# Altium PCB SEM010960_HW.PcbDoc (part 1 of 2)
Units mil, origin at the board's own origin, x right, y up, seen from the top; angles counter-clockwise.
Board outline 2559.06 x 1889.76 mil, 2 copper layers (Top Layer, Bottom Layer), stack 62 mil thick; 97 components, 58 nets, 246 pads, 75 vias.
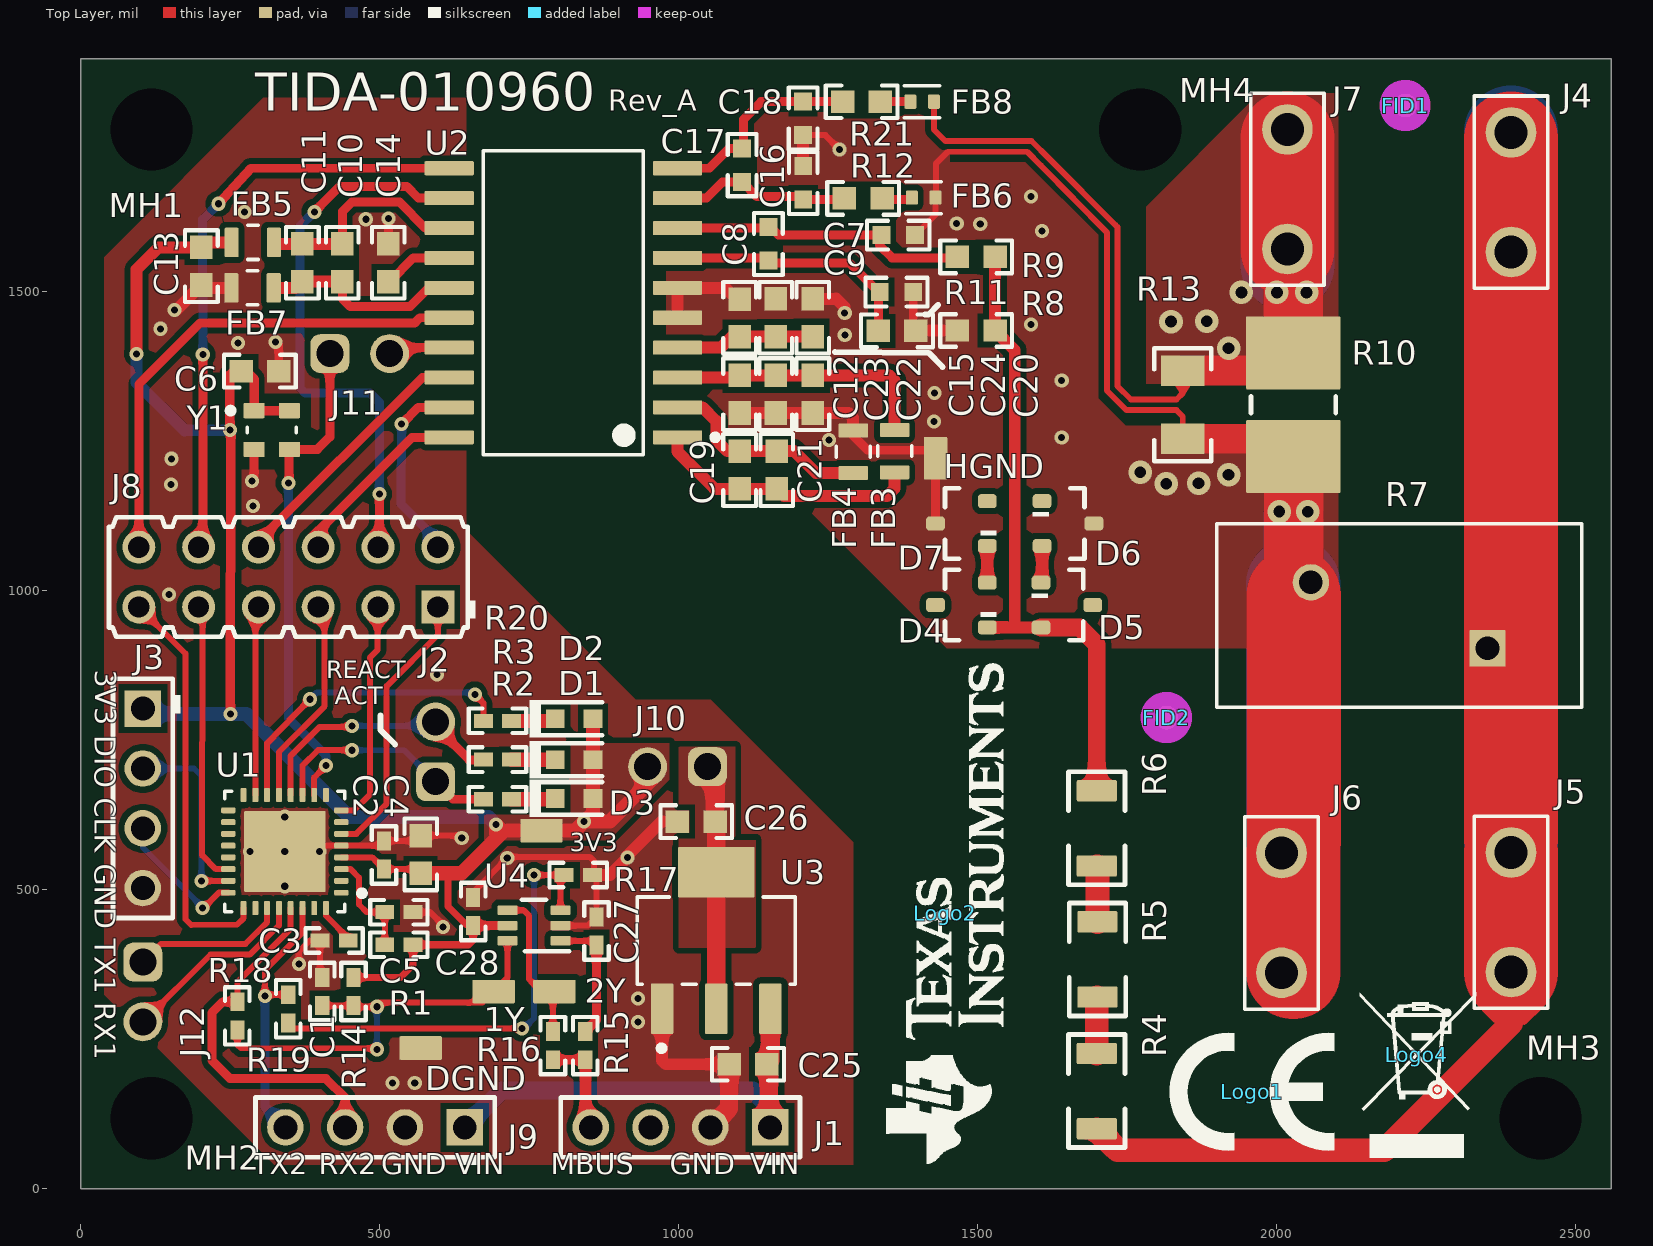
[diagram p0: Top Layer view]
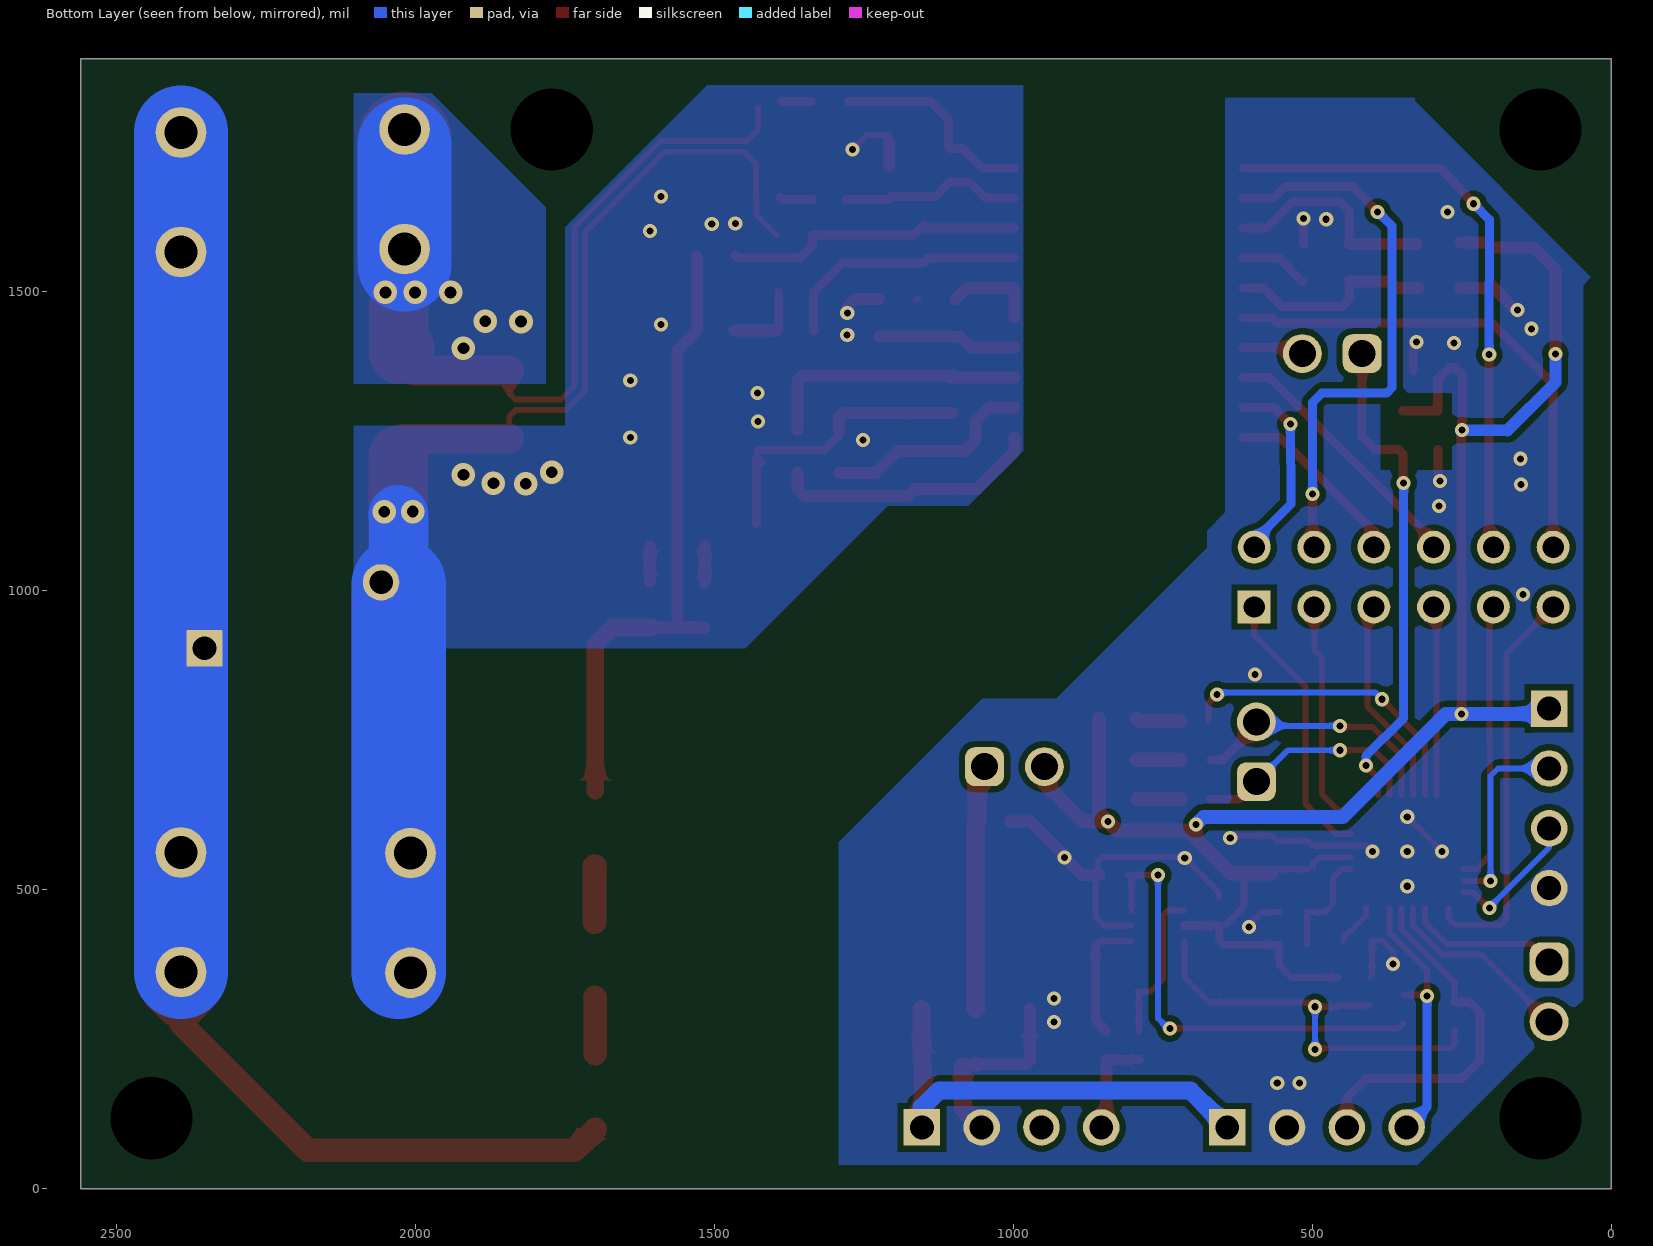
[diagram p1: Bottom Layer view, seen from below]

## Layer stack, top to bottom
Top Solder: solder mask 0.4, Solder Resist, Dk 3.5
Top Layer: signal copper 1.4
Dielectric1: core 59.2, FR-4 High Tg, Dk 4.8
Bottom Layer: signal copper 1.4
Bottom Solder: solder mask 0.4, Solder Resist, Dk 3.5

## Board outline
0,0 2559.06,0 2559.06,1889.76 0,1889.76

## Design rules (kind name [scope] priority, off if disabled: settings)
AcuteAngle [All] p1: minimum=1.50000000000000E+0001 checktracksonly=FALSE
AssemblyTestPointUsage [All] p1: valid=2
BoardOutlineClearance BoardOutlineClearance_MountingHoles [OnCopper and InComponentClass('Mounting Holes')] p1: gap=39.37 ignorepadtopadclearanceinfootprint=FALSE
BoardOutlineClearance BoardOutlineClearance_Poly [OnCopper and IsPoly] p2: gap=25 ignorepadtopadclearanceinfootprint=FALSE
BoardOutlineClearance [OnCopper and Not InComponentClass('Logo') and not InComponentClass('FiducialMark') and not InRegion(1000,500,4000,800) and not InPoly] p3: gap=40 ignorepadtopadclearanceinfootprint=FALSE
Clearance Clearance_Keepouts [((IsTrack Or IsArc) And Not InPoly) And IsFree and IsKeepOut vs ((IsTrack Or IsArc) And Not InPoly) And IsFree and IsKeepOut] p1: gap=0 ignorepadtopadclearanceinfootprint=FALSE
Clearance Clearance_Poly [InPolygon] p2: gap=10 ignorepadtopadclearanceinfootprint=TRUE
Clearance Clearance_FiducialMark [IsKeepOut and InComponentClass('FiducialMark') vs IsPad and InComponentClass('FiducialMark')] p3: gap=0 ignorepadtopadclearanceinfootprint=FALSE
Clearance [All] p4: gap=7.87 ignorepadtopadclearanceinfootprint=TRUE
ComponentClearance ComponentClearance_MountingHoles_FiducialMarks [InComponentClass('Mounting Holes') vs InComponentClass('FiducialMark')] p1: gap=50 collisioncheckmode=3 verticalgap=10 showdistances=FALSE
ComponentClearance ComponentClearance_Shunt [InComponentClass('Header') vs InComponentClass('Shunt')] p2: gap=0 collisioncheckmode=3 verticalgap=0 showdistances=FALSE
ComponentClearance ComponentClearance_Logo [InComponentClass('Logo')] p3: gap=30 collisioncheckmode=3 verticalgap=10 showdistances=FALSE
ComponentClearance ComponentClearance_ScrewToNut [(HasFootprint('NY PMS 440 0025 PH')) vs (HasFootprint('Keystone_1902C'))] p4: gap=5 collisioncheckmode=3 verticalgap=10 showdistances=FALSE
ComponentClearance ComponentClearance_MountingHoles [InComponentClass('Mounting Holes')] p5: gap=100 collisioncheckmode=3 verticalgap=100000 showdistances=FALSE
ComponentClearance ComponentClearance_SmallPassives [HasFootprint('0201*') or HasFootprint('0402*') or HasFootprint('0508') or HasFootprint('0603*') or HasFootprint('0612') or HasFootprint('0805*') or HasFootprint('0815*') or HasFootprint('0830*') or HasFootprint('1206*') or HasFootprint('1210*') or HasFootprint('1808*') or HasFootprint('1812*') or HasFootprint('1825*') or HasFootprint('2010*') or HasFootprint('2220*') or HasFootprint('2225*') or HasFootprint('2512*') or HasFootprint('2728*') or HasFootprint('3518*') vs HasFootprint('0201*') or HasFootprint('0402*') or HasFootprint('0508') or HasFootprint('0603*') or HasFootprint('0612') or HasFootprint('0805*') or HasFootprint('0815*') or HasFootprint('0830*') or HasFootprint('1206*') or HasFootprint('1210*') or HasFootprint('1808*') or HasFootprint('1812*') or HasFootprint('1825*') or HasFootprint('2010*') or HasFootprint('2220*') or HasFootprint('2225*') or HasFootprint('2512*') or HasFootprint('2728*') or HasFootprint('3518*')] p6: gap=14.96 collisioncheckmode=3 verticalgap=10 showdistances=FALSE
ComponentClearance ComponentClearance_THtoSMT [IsThruComponent vs IsSMTComponent] p7: gap=10 collisioncheckmode=3 verticalgap=10 showdistances=FALSE
ComponentClearance ComponentClearance_THtoTH [IsThruComponent vs IsThruComponent] p8: gap=20 collisioncheckmode=3 verticalgap=30 showdistances=FALSE
ComponentClearance [All] p9: gap=10 collisioncheckmode=3 verticalgap=10 showdistances=FALSE
DiffPairsRouting [All] p1: maxlimit=100 minlimit=10 mostfreqgap=10 toplayer_minwidth=15 toplayer_maxwidth=15 toplayer_prefwidth=15 bottomlayer_minwidth=15 bottomlayer_maxwidth=15 bottomlayer_prefwidth=15 maxuncoupledlength=1000
FabricationTestPointUsage TestPointUsage [All] p1: valid=2 allowmultiple=FALSE
FabricationTestpoint Testpoint [All] p1: side=3 testpointundercomponent=TRUE minsize=40 maxsize=100 preferedsize=60 minholesize=0 maxholesize=40 preferedholesize=32 testpointgrid=1 allowsidetop=TRUE allowsidebottom=TRUE usegrid=TRUE gridtolerance=0.01
FanoutControl Fanout_LCC [IsLCC] p1: bgadir=Out bgaviamode=Centered fanoutstyle=Auto fanoutdirection=Alternating viagrid=1 // Fanout_LCC (Default Rule)
FanoutControl Fanout_BGA [IsBGA] p2: bgadir=Out bgaviamode=Centered fanoutstyle=Auto fanoutdirection=Alternating viagrid=1 // Fanout_BGA (Default Rule)
FanoutControl Fanout_Default [All] p4: bgadir=Out bgaviamode=Centered fanoutstyle=Auto fanoutdirection=Alternating viagrid=1 // Fanout_Default (Default Rule)
FanoutControl Fanout_Small [(CompPinCount < 5)] p5: bgadir=Out bgaviamode=Centered fanoutstyle=Auto fanoutdirection=OutThenIn viagrid=1 // Fanout_Small (Default Rule)
HoleSize [All] p1: absolutevalues=TRUE maxlimit=251 minlimit=5 maxpercent=80.000 minpercent=20.000
MinimumAnnularRing MinimumAnnularRing_ThermalPadVias [IsVia and InAnyComponent] p1: minimumring=5.91
MinimumAnnularRing [All] p2: minimumring=5
MinimumSolderMaskSliver MinimumSolderMaskSliver_Logo [InComponentClass('Logo') vs InComponentClass('Logo')] p1: minsoldermaskwidth=0.7
MinimumSolderMaskSliver [All] p2: minsoldermaskwidth=0
PlaneConnect [All] p1: planeconnectstyle=Direct reliefexpansion=10 reliefentries=4 reliefconductorwidth=10 reliefairgap=10
PolygonConnect [All] p1: connectstyle=Direct reliefconductorwidth=10 reliefentries=4 polygonreliefangle="90 Angle" airgapwidth=10
RoutingVias ThermalPadVias [IsVia and InAnyComponent] p1: holewidth=7.87 width=19.68 viastyle="Through Hole" minholewidth=7.87 minwidth=19.68 maxholewidth=12.99 maxwidth=23.62
RoutingVias [All] p2: holewidth=16 width=34 viastyle="Through Hole" minholewidth=5 minwidth=5 maxholewidth=40 maxwidth=65
SilkToBoardRegionClearance [Not ((IsComment or IsDesignator) And (Hide <> 'False')) and not InRegion(1000,500,4000,800)] p1:
SilkToSilkClearance SilkToSilkClearance_Pb-FreeLogo [(HasFootprint('Pb-Free_Overlay_Medium') OR HasFootprint('Pb-Free_Overlay_Small')) vs (HasFootprint('Pb-Free_Overlay_Medium') OR HasFootprint('Pb-Free_Overlay_Small'))] p1: silktosilkclearance=0
SilkToSilkClearance [All] p2: silktosilkclearance=0
SilkToSolderMaskClearance SilkToComponentPadClearance [(IsPad or IsFill or IsRegion) and InAnycomponent] p1: minsilkscreentomaskgap=0 clearancetoexposedcopper=TRUE
SilkToSolderMaskClearance "Silk to Solder Mask Opening" [All] p2: minsilkscreentomaskgap=0 clearancetoexposedcopper=FALSE
SolderMaskExpansion [All] p1: expansion=1.97 istentingtop=FALSE
UnRoutedNet [All] p1: checkbadconnections=TRUE
Width [All] p1: maxlimit=157.48 minlimit=6 preferedwidth=10 checkconnectedcopper=TRUE
14 further rules are at their usual default settings.

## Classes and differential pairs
component class SEM010960_HW_MSPM0: 1Y 2Y 3V3 C1 C2 C3 C4 C5 C6 C25 C26 C27 C28 D1 D2 D3 J1 J2 J3 J8 J9 J10 J12 R1 R2 R3 R14 R15 R16 R17 R18 R19 R20 U1 U3 U4 Y1
component class SEM010960_HW_AMC: C7 C8 C9 C10 C11 C12 C13 C14 C15 C16 C17 C18 C19 C20 C21 C22 C23 C24 D4 D5 D6 D7 DGND FB3 FB4 FB5 FB6 FB7 FB8 HGND J4 J5 J6 J7 J11 R4 R5 R6 R7 R8 R9 R10 R11 R12 R13 R21 U2
component class Header: J1 J2 J3 J8 J9 J10 J11 J12
component class Logo: Logo2
component class SEM010960_HW_Hardware: FID1 FID2 Logo1 Logo2 Logo4 MH1 MH2 MH3 MH4 ZZ1 ZZ2 ZZ3 ZZ4
component class FiducialMark: FID1 FID2
component class AssemblyNote: ZZ1 ZZ2 ZZ3 ZZ4

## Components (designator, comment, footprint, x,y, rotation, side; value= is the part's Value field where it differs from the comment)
1Y "Testpoint_Gray" Harwin_S2761-46R 690.22,330.04 r180 top
2Y "Testpoint_Gray" Harwin_S2761-46R 791.78,330.04 r180 top
3V3 "Testpoint_Gray" Harwin_S2761-46R 770.28,599.28 r180 top
C1 "C0402C101J3GACTU" 0402 403.54,330.04 r90 top value=100pF
C2 "GRM155R61A105KE15D" 0402 506.78,558.33 r90 top value=1uF
C3 "GRM155R61C474KE01" 0402 423.49,415.31 r0 top value=0.47uF
C4 "GRM188R61A106KAALD" 0603 568.12,559.29 r270 top value=10uF
C5 "C1005X7R1C103K050BA" 0402 531.78,462.82 r0 top value=0.01uF
C6 "LMK107B7105KA-T" 0603 299.36,1367.63 r0 top value=1uF
C7 "885012006057" 0603_HV 1366.91,1595.02 r0 top value=100pF
C8 "C0603C472J1GAC7867" 0603_HV 1149.9,1580.32 r270 top value=4700pF
C9 "885012006057" 0603_HV 1364,1499.91 r180 top value=100pF
C10 "C0603C102K5RACTU" 0603 437.16,1548.83 r270 top value=1000pF
C11 "C0603C105K3RACTU" 0603 370.41,1548.83 r90 top value=1uF
C12 "885012006057" 0603 1101.57,1329.08 r90 top value=100pF
C13 "C0603C105K3RACTU" 0603 201.52,1543.15 r90 top value=1uF
C14 "C1608X7R1H104K080AA" 0603 514.1,1548.83 r90 top value=0.1uF
C15 "885012006057" 0603 1101.57,1456.52 r270 top value=100pF
C16 "885012006057" 0603_HV 1207.99,1682.52 r90 top value=100pF
C17 "C0603C472J1GAC7867" 0603_HV 1105.92,1712.12 r90 top value=4700pF
C18 "885012006057" 0603_HV 1207.7,1790.18 r90 top value=100pF
C19 "C0603C102K5RACTU" 0603 1101.57,1202.29 r90 top value=1000pF
C20 "C1608X7R1H104K080AA" 0603 1223.92,1456.91 r90 top value=0.1uF
C21 "C0603C105K3RACTU" 0603 1163.8,1202.29 r270 top value=1uF
C22 "C1608X7R1H104K080AA" 0603 1224.17,1329.08 r270 top value=0.1uF
C23 "C0603C102K5RACTU" 0603 1162.23,1329.08 r270 top value=1000pF
C24 "C0603C102K5RACTU" 0603 1162.23,1456.91 r90 top value=1000pF
C25 "CGA3E1X7R1V105K080AE" 0603 1115.61,208.42 r180 top value=1uF
C26 "GRM188Z71C225KE43" 0603 1029.13,614.27 r180 top value=2.2uF
C27 "C0402C101J3GACTU" 0402 862.2,431.33 r90 top value=100pF
C28 "04023C103JAT2A" 0402 655.94,463.84 r90 top value=0.01uF
D1 "150060VS75000" WL-SMCW_GREEN 824.74,653.05 r0 top value=Green
D2 "150060YS75000" WL-SMCW_YELLOW 824.74,717.62 r0 top value=Yellow
D3 "150060RS75000" WL-SMCW_RED 824.74,786.21 r0 top value=Red
D4 "BAV199-TP" SOT-23L 1472.56,976.43 r180 top value=70V
D5 "BAV199-TP" SOT-23L 1648.9,976.43 r0 top value=70V
D6 "BAV199-TP" SOT-23L 1650.78,1112.76 r0 top value=70V
D7 "BAV199-TP" SOT-23L 1472.56,1112.76 r180 top value=70V
DGND "Testpoint_Gray" Harwin_S2761-46R 568.12,235.62 r180 top
FB3 "BLM21HE472SH1L" FP-BLM21HE472SH1L_0805-MFG 1360.91,1233.79 r90 top
FB4 "BLM21HE472SH1L" FP-BLM21HE472SH1L_0805-MFG 1291.55,1232.81 r90 top
FB5 "BLM21HE472SH1L" FP-BLM21HE472SH1L_0805-MFG 287.53,1582.83 r180 top
FB6 "74269244182" FP-74269244182_0402-MFG 1409.42,1657.7 r0 top
FB7 "BLM21HE472SH1L" FP-BLM21HE472SH1L_0805-MFG 286.99,1506.91 r180 top
FB8 "74269244182" FP-74269244182_0402-MFG 1406.9,1818.18 r0 top
FID1 "Fiducial" Fiducial10-20 2214.57,1811.83 r0 top
FID2 "Fiducial" Fiducial10-20 1815.21,788.17 r0 top
HGND "Testpoint_Gray" Harwin_S2761-46R 1429.25,1222.13 r270 top
J1 "PBC04SAAN" Sullins_xxC04SAAN 1002.59,102.93 r180 top
J2 "61300211121" WURTH_61300211121 593.26,731.01 r90 top
J3 "PBC04SAAN" Sullins_xxC04SAAN 103.57,653.05 r270 top
J4 "63824-1" FP-63824-1_CONN_7MM92_3MM11-MFG 2391.73,1666.9 r90 top
J5 "63824-1" FP-63824-1_CONN_7MM92_3MM11-MFG 2391.73,462.6 r270 top
J6 "63824-1" FP-63824-1_CONN_7MM92_3MM11-MFG 2007.87,461.48 r270 top
J7 "63824-1" FP-63824-1_CONN_7MM92_3MM11-MFG 2017.72,1671.9 r270 top
J8 "802-10-012-10-001000" Mill-Max_802-10-012-10-001000 346.88,1023.2 r180 top
J9 "PBC04SAAN" Sullins_xxC04SAAN 491.91,102.93 r180 top
J10 "61300211121" WURTH_61300211121 997.78,706.13 r180 top
J11 "61300211121" WURTH_61300211121 466.29,1396.93 r0 top
J12 "61300211121" WURTH_61300211121 103.57,329.33 r270 top
Logo1 "CE Mark" CE_Mark_5mm 1958.66,162.33 r0 top
Logo2 "Texas Instruments" TI_Stacked_Overlay_Small 1445.3,460.66 r90 top
Logo4 "WEEE logo" WEEE_Minimum 2234.25,224.41 r0 top
MH1 "MTG_NoPads" NPTH125mil#1 105.6,1764.12 r0 top
MH2 "MTG_NoPads" NPTH125mil#2 118.11,118.11 r0 top
MH3 "MTG_NoPads" NPTH125mil#3 2450.79,127.95 r0 top
MH4 "MTG_NoPads" NPTH125mil#4 1771.65,1736.37 r0 top
R1 "RC0402FR-0747KL" 0402 531.78,408.3 r0 top value=47.0k
R2 "RC0402FR-07820RL" 0402 696.7,651.64 r0 top value=820
R3 "RC0402FR-07820RL" 0402 696.7,717.95 r0 top value=820
R4 "TNPV1206330KBEEN" TNPV1206 1698.88,163.57 r270 top value=330k
R5 "TNPV1206330KBEEN" TNPV1206 1699.92,383.68 r270 top value=330k
R6 "TNPV1206330KBEEN" TNPV1206 1698.88,602.9 r90 top value=330k
R7 "B72214S2461K101" FP-B72214S2461K101_RADIAL-MFG 2204.72,959.21 r180 top
R8 "RG1608P-751-B-T5" 0603 1497.28,1435.59 r0 top value=750
R9 "CRCW060349R9FKEA" 0603 1497.28,1558.67 r180 top value=49.9
R10 "CRE2512-FZ-R003E-3" CRE2512-R1_R4 2027.56,1311.46 r270 top value=0.003
R11 "CRCW060349R9FKEA" 0603 1364.86,1434.86 r180 top value=49.9
R12 "CRCW060349R9FKEA" 0603 1308.29,1656.49 r180 top value=49.9
R13 "CRF1206-FZ-R001ELF" 1206 1842.71,1311.46 r270 top value=0.001
R14 "CRCW040210K0DHEDP" 0402 455.94,330.04 r90 top value=10.0k
R15 "CRCW040210K0DHEDP" 0402 843.53,239.71 r270 top value=10.0k
R16 "CRCW040210R0FKED" 0402 789.37,239.71 r270 top value=10.0
R17 "CRCW040210K0DHEDP" 0402 831.72,524.84 r180 top value=10.0k
R18 "RC0402JR-070RL" 0402 261.68,289.33 r270 top value=0
R19 "RC0402JR-070RL" 0402 346.85,301.14 r270 top value=0
R20 "RC0402FR-07820RL" 0402 696.7,782.68 r0 top value=820
R21 "CRCW060349R9FKEA" 0603 1305.52,1818.18 r180 top value=49.9
U1 "MSPM0G1106TRHBR" RHB0032N-MFG 340.94,564.23 r180 top
U2 "AMC131M03DFM" DFM0020A-MFG 806.83,1481.91 r180 top
U3 "TLV76133DCYR" DCY0004A-MFG 1062.59,415.31 r90 top
U4 "SN74LVC2G07DCKT" DCK0006A_N 757.73,440.38 r180 top
Y1 "LMK6CxxxDLF" DLF0004A-MFG 319.15,1269.09 r0 top
ZZ1 "This Assembly Note is for PCB labels only" AssemblyNoteLabel 185,3938 r0 top
ZZ2 "These assemblies are ESD sensitive, ESD precautions shall be observed." AssemblyNote 185,3829.11 r0 top
ZZ3 "These assemblies must be clean and free from flux and all contaminants. Use of no clean flux is not acceptable." AssemblyNote 185,3740.56 r0 top
ZZ4 "These assemblies must comply with workmanship standards IPC-A-610 Class 2, unless otherwise specified." AssemblyNote 185,3652 r0 top

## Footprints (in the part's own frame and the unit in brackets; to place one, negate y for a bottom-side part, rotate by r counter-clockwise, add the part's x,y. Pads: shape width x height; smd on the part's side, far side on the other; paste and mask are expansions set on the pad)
0402 [mm] "0402 from SM-752 data"
  rect 0.8x0.6 smd: 1(-0.6,0) 2(0.6,0)
  silkscreen extent -1.22,-0.52 1.22,0.52, body extent -0.55,-0.3 0.55,0.3, height 0.6
0603 [mm] "0603 from SM-752 data"
  rect 1x0.95 smd: 1(-0.8,0) 2(0.8,0)
  silkscreen extent -1.52,-0.69 1.52,0.69, body extent -0.87,-0.47 0.87,0.47, height 1
0603_HV [mil] "Ernesto recommended land pattern.  26 mil between pads."
  rect 30x30 smd: 1(-28,0) 2(28,0)
  silkscreen extent -52,-24 52,24, body extent -34,-19 34,19, height 39
1206 [mm] "1206 from SM-752 data"
  rect 1.3x1.85 smd: 1(-1.45,0) 2(1.45,0)
  silkscreen extent -2.4,-1.21 2.4,1.21, body extent -1.7,-0.9 1.7,0.9, height 1.35
AssemblyNote [mil] "Assembly Note"
AssemblyNoteLabel [mil] "Assembly Note for PCB Labels"
CE_Mark_5mm [mil] "Minimum text height for CE Mark"
  silkscreen extent -138,-98 138,98
CRE2512-R1_R4 [mm] "SMD, 2-Leads, Body 6.45x3.35mm"
  rrect3% 3.1x4 smd: 1(-2.2,0) 2(2.2,0)
  silkscreen extent -0.35,-1.8 0.35,1.8, body extent -3.32,-1.77 3.33,1.78, height 0.9
DCK0006A_N [mm] "SOT23, 6-Leads, Body 2x1.3mm, Pitch 0.65mm, Lead Span 2.1mm, IPC Medium Density"
  rrect25% 0.85x0.4 smd: 1(-1.125,0.65) 2(-1.125,0) 3(-1.125,-0.65) 4(1.125,-0.65) 5(1.125,0) 6(1.125,0.65)
  silkscreen extent -1.5,-1.09 0.51,1.09, body extent -1.14,-1 1.14,1, height 0.95
DCY0004A-MFG [mm]
  rrect11% 2.15x0.95 smd paste+0 mask+0: 1(-2.9,2.3) 2(-2.9,0) 3(-2.9,-2.3)
  rrect5% 2.15x3.25 smd paste+0 mask+0: 4(2.9,0)
  silkscreen extent -4.7,-3.35 1.85,3.35, body extent -4.08,-3.45 4.08,3.45, height 0.25
DFM0020A-MFG [mm]
  rrect17% 2.1x0.6 smd paste+0 mask+0: 1(-4.85,5.715) 2(-4.85,4.445) 3(-4.85,3.175) 4(-4.85,1.905) 5(-4.85,0.635) 6(-4.85,-0.635) 7(-4.85,-1.905) 8(-4.85,-3.175) 9(-4.85,-4.445) 10(-4.85,-5.715) 11(4.85,-5.715) 12(4.85,-4.445) 13(4.85,-3.175) 14(4.85,-1.905) 15(4.85,-0.635) 16(4.85,0.635) 17(4.85,1.905) 18(4.85,3.175) 19(4.85,4.445) 20(4.85,5.715)
  silkscreen extent -6.57,-6.47 3.4,6.47, body extent -6,-6.72 6,6.72, height 0.25
DLF0004A-MFG [mm]
  rrect15% 0.9x0.65 smd paste-1000 mask+0: 1(-0.75,0.825) 2(-0.75,-0.825) 3(0.75,-0.825) 4(0.75,0.825)
  silkscreen extent -1.87,-0.13 1.05,0.95, body extent -1.3,-1.4 1.3,1.4, height 0.25
Fiducial10-20 [mm]
  round 1 smd mask+0.5: 1(0,0)
  Top Layer keep-out circle w1.178: c0,0 r0.5
FP-63824-1_CONN_7MM92_3MM11-MFG [mm]
  round 2.15 hole 1.4 paste-1000 mask+0: 1(-2.54,0) 1(2.54,0)
  silkscreen extent -4.09,-1.56 4.09,1.56, body extent -3.96,-1.54 3.96,1.54, height 10.88
FP-74269244182_0402-MFG [mm]
  rrect20% 0.5x0.6 smd paste+0 mask+0: 1(-0.5,0) 2(0.5,0)
  silkscreen extent -0.75,-0.67 0.75,0.67, body extent -0.85,-0.4 0.85,0.4, height 0.25
FP-B72214S2461K101_RADIAL-MFG [mm]
  rrect6% 1.55x1.55 hole 1 paste-1000 mask+0: 1(-3.75,1.4)
  round 1.55 hole 1 paste-1000 mask+0: 2(3.75,-1.4)
  silkscreen extent -7.75,-3.9 7.75,3.9, body extent -7.85,-4 7.85,4, height 0.25
FP-BLM21HE472SH1L_0805-MFG [mm]
  rrect17% 0.6x1.25 smd paste+0 mask+0: 1(-0.9,0) 2(0.9,0)
  silkscreen extent -0.23,-0.72 0.23,0.72, body extent -1.3,-0.82 1.3,0.82, height 0.25
Harwin_S2761-46R [mm] "Natural PC Test Point Brass, SMT"
  rrect10% 1.8x1 smd: 1(0,0)
  body extent -0.8,-0.4 0.8,0.4, height 1.15
Mill-Max_802-10-012-10-001000 [mm] "Header, 2.54 mm, 6x2, TH"
  rect 1.4x1.4 hole 0.9: 1(-6.35,1.27)
  round 1.4 hole 0.9: 2(-6.35,-1.27) 3(-3.81,1.27) 4(-3.81,-1.27) 5(-1.27,1.27) 6(-1.27,-1.27) 7(1.27,1.27) 8(1.27,-1.27) 9(3.81,1.27) 10(3.81,-1.27) 11(6.35,1.27) 12(6.35,-1.27)
  silkscreen extent -7.96,-2.54 7.62,2.54, body extent -7.62,-2.54 7.62,2.54, height 8.11
NPTH125mil#1 [mm]
  round 3.2 hole 3.5 unplated mask+0.381: 1(0.318,0.191)
NPTH125mil#2 [mm]
  round 3.2 hole 3.5 unplated mask+0.381: 1(0,0)
NPTH125mil#3 [mm]
  round 3.2 hole 3.5 unplated mask+0.381: 1(-0.25,-0.25)
NPTH125mil#4 [mm]
  round 3.2 hole 3.5 unplated mask+0.381: 1(0,0.896)
RHB0032N-MFG [mm]
  rrect40% 0.6x0.25 smd paste+0 mask+0: 1(-2.4,1.75) 2(-2.4,1.25) 3(-2.4,0.75) 4(-2.4,0.25) 5(-2.4,-0.25) 6(-2.4,-0.75) 7(-2.4,-1.25) 8(-2.4,-1.75) 17(2.4,-1.75) 18(2.4,-1.25) 19(2.4,-0.75) 20(2.4,-0.25) 21(2.4,0.25) 22(2.4,0.75) 23(2.4,1.25) 24(2.4,1.75)
  rrect40% 0.25x0.6 smd paste+0 mask+0: 9(-1.75,-2.4) 10(-1.25,-2.4) 11(-0.75,-2.4) 12(-0.25,-2.4) 13(0.25,-2.4) 14(0.75,-2.4) 15(1.25,-2.4) 16(1.75,-2.4) 25(1.75,2.4) 26(1.25,2.4) 27(0.75,2.4) 28(0.25,2.4) 29(-0.25,2.4) 30(-0.75,2.4) 31(-1.25,2.4) 32(-1.75,2.4)
  rrect3% 3.45x3.45 smd paste-1000 mask+0: 33(0,0)
  silkscreen extent -3.4,-2.55 2.55,2.55, body extent -2.8,-2.8 2.8,2.8, height 0.25
SOT-23L [mm] "SOT23, 3-Leads, Body 2.9x1.3mm, Pitch 0.95mm, Lead Span 2.5mm, IPC High Density"
  rrect50% 0.8x0.6 smd: 1(-1.1,0.95) 2(-1.1,-0.95) 3(1.1,0)
  silkscreen extent -1.5,-1.5 0.7,1.5, body extent -1.16,-1.45 1.21,1.45, height 1
Sullins_xxC04SAAN [mm] "Header, 2.54 mm, 4x1, TH"
  rect 1.55x1.55 hole 1.016: 1(-3.81,0)
  round 1.55 hole 1.016: 2(-1.27,0) 3(1.27,0) 4(3.81,0)
  silkscreen extent -5.08,-1.27 5.08,1.6, body extent -5.08,-1.27 5.08,1.27, height 8.38
TI_Stacked_Overlay_Small [mil]
  silkscreen extent -418,-98 418,98
TNPV1206 [mm] "VISHAY"
  rrect11% 0.9x1.7 smd: 1(-1.6,0) 2(1.6,0)
  silkscreen extent -2.4,-1.2 2.4,1.2, body extent -1.67,-0.87 1.67,0.87, height 0.65
WEEE_Minimum [mil] "WEEElie bin"
  silkscreen extent -95,-172 99,104
WL-SMCW_GREEN [mm] "WURTH"
  rect 0.8x0.8 smd: 1(-0.8,0) 2(0.8,0)
  silkscreen extent -1.9,-0.8 1.2,0.8, body extent -0.85,-0.45 0.85,0.45, height 0.8
WL-SMCW_RED [mm] "WURTH"
  rect 0.8x0.8 smd: 1(-0.8,0) 2(0.8,0)
  silkscreen extent -1.9,-0.8 1.2,0.8, body extent -0.85,-0.45 0.85,0.45, height 0.8
WL-SMCW_YELLOW [mm] "WURTH"
  rect 0.8x0.8 smd: 1(-0.8,0) 2(0.8,0)
  silkscreen extent -1.9,-0.8 1.2,0.8, body extent -0.85,-0.45 0.85,0.45, height 0.8
WURTH_61300211121 [mm] "Header, 2.54mm, 2x1, TH"
  rrect50% 1.65x1.65 hole 1.15: 1(-1.27,0)
  round 1.65 hole 1.15: 2(1.27,0)
  body extent -2.54,-1.27 2.54,1.27, height 8.54

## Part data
1Y 2Y 3V3 DGND HGND: library part CMP-0067619-1, "Natural PC Test Point Brass, SMT", Manufacturer=Harwin, PartNumber=S2761-46R, Supplier Part Number 1=952-2665-1-ND
C1 C27: library part CMP-0006233-2, "CAP, CERM, 100 pF, 25 V, +/- 5%, C0G/NP0, 0402", Cap_Case=0402, Manufacturer=Kemet, Supplier Part Number 1=399-1022-1-ND, TempCo=C0G/NP0, Tolerance_%=5%, Value1=Unknown, Value2=25V, ValueDisplayed=100pF
C2: library part CMP-0006563-2, "CAP, CERM, 1 uF, 10 V, +/- 10%, X5R, 0402", Cap_Case=0402, Manufacturer=MuRata, Supplier Part Number 1=490-3890-1-ND, TempCo=X5R, Tolerance_%=10%, Value1=Unknown, Value2=10V, ValueDisplayed=1uF
C3: library part CMP-0006600-2, "CAP, CERM, 0.47 uF, 16 V, +/- 10%, X5R, 0402", Cap_Case=0402, Manufacturer=MuRata, TempCo=X5R, Tolerance_%=10%, Value1=Unknown, Value2=16V, ValueDisplayed=0.47uF
C4: library part CMP-0086193-1, "CAP, CERM, 10 µF, 10 V,+/- 10%, X5R, 0603", Cap_Case=0603, Manufacturer=MuRata, TempCo=X5R, Tolerance_%=10%, Value2=10V, ValueDisplayed=10µF
C5: library part CMP-0006292-2, "CAP, CERM, 0.01 uF, 16 V, +/- 10%, X7R, 0402", Cap_Case=0402, Manufacturer=TDK, Supplier Part Number 1=445-1262-1-ND, TempCo=X7R, Tolerance_%=10%, Value1="0.0623 ohm", Value2=16V, ValueDisplayed=0.01uF
C6: library part CMP-0080632-1, "CAP, CERM, 1 µF, 10 V,+/- 10%, X7R, 0603", Cap_Case=0603, Manufacturer="Taiyo Yuden", Supplier Part Number 1=587-1242-1-ND, TempCo=X7R, Tolerance_%=10%, Value2=10V, ValueDisplayed=1µF
C7 C9 C12 C15 C16 C18: library part CMP-0006822-4, "CAP, CERM, 100 pF, 50 V, +/- 5%, C0G/NP0, 0603", Cap_Case=0603, Manufacturer="Wurth Elektronik", TempCo=C0G/NP0, Tolerance_%=5%, Value1=Unknown, Value2=50V, ValueDisplayed=100pF
C8 C17: library part CMP-0006941-4, "CAP, CERM, 4700 pF, 100 V, +/- 5%, C0G/NP0, 0603", Cap_Case=0603, Manufacturer=Kemet, Supplier Part Number 1=399-9974-1-ND, TempCo=C0G/NP0, Tolerance_%=5%, Value1=Unknown, Value2=100V, ValueDisplayed=4700pF
C10 C19 C23 C24: library part CMP-0006847-4, "CAP, CERM, 1000 pF, 50 V, +/- 10%, X7R, 0603", Cap_Case=0603, Manufacturer=Kemet, Supplier Part Number 1=399-1082-1-ND, TempCo=X7R, Tolerance_%=10%, Value1=Unknown, Value2=50V, ValueDisplayed=1000pF
C11 C13 C21: library part CMP-0006867-4, "CAP, CERM, 1 uF, 25 V, +/- 10%, X7R, 0603", Cap_Case=0603, Manufacturer=Kemet, Supplier Part Number 1=399-7376-1-ND, TempCo=X7R, Tolerance_%=10%, Value1=Unknown, Value2=25V, ValueDisplayed=1uF
C14 C20 C22: library part CMP-0007044-5, "CAP, CERM, 0.1 uF, 50 V, +/- 10%, X7R, 0603", Cap_Case=0603, Manufacturer=TDK, Supplier Part Number 1=445-1314-1-ND, TempCo=X7R, Tolerance_%=10%, Value1="0.0296 ohm", Value2=50V, ValueDisplayed=0.1uF
C25: library part CMP-0081259-1, "CAP, CERM, 1 µF, 35 V,+/- 10%, X7R, AEC-Q200 Grade 1, 0603", Cap_Case=0603, Manufacturer=TDK, Supplier Part Number 1=445-174339-1-ND, TempCo=X7R, Tolerance_%=10%, Value2=35V, ValueDisplayed=1µF
C26: library part CMP-0007499-1, "CAP, CERM, 2.2 uF, 16 V, +/- 10%, X7R, 0603", Cap_Case=0603, Manufacturer=MuRata, Supplier Part Number 1=81-GRM188Z71C225KE3D, TempCo=X7R, Tolerance_%=10%, Value1=Unknown, Value2=16V, ValueDisplayed=2.2uF
C28: library part CMP-0085568-1, "CAP, CERM, 0.01 µF, 25 V,+/- 5%, X7R, 0402", Cap_Case=0402, Manufacturer=AVX, TempCo=X7R, Tolerance_%=5%, Value2=25V, ValueDisplayed=0.01µF
D1: library part CMP-0002894-2, "LED, Green, SMD", Color=green, Manufacturer="Wurth Elektronik", Value1=W, Value2=2V
D2: library part CMP-0002892-3, "LED, Yellow, SMD", Color=yellow, Manufacturer="Wurth Elektronik", Value1=W, Value2=2V
D3: library part CMP-0002947-2, "LED, Red, SMD", Color=Red, Manufacturer="Wurth Elektronik", Power_TotalModule=72mW, Supplier Part Number 1=732-4978-1-ND, Value1=0.072W, Value2=2V
D4 D5 D6 D7: library part CMP-0076968-2, "Diode, Switching, 70 V, 0.215 A, SOT-23", Manufacturer="Micro Commercial Components", Value1=0.215A, Value2=V
FB3 FB4 FB5 FB7: library part CMP-0037616-1, "4.7 kOhms @ 100 MHz 1 Signal Line Ferrite Bead 0805 (2012 Metric) 850mA 400mOhm", Digikey Part Number=490-BLM21HE472SH1LCT-ND, Impedance At Frequency="4700Ω @ 100MHz", Manufacturer=Murata, Mouser Part Number=81-BLM21HE472SH1L, Operating Temperature Range="-55°C to +125°C"
FB6 FB8: library part CMP-0091663-1, "1.8 kOhms @ 100MHz 1 Power, Signal Line Ferrite Bead 0402 (1005 Metric) 210mA 2.1Ohm", Digikey Part Number=732-74269244182CT-ND, Impedance At Frequency="1800Ω @ 100MHz", Manufacturer="Wurth Electronics", Mouser Part Number=710-74269244182, Operating Temperature Range="-55°C to +125°C", Test Frequency=1GHz, Tolerance_%=25%
FID1 FID2: library part CMP-0077181-1, "Fiducial mark.  There is nothing to buy or mount.", Manufacturer=N/A
J1 J3 J9: library part CMP-0054583-1, "Header, 2.54 mm, 4x1, Gold, TH", Color=Black, Current_A=3A, Manufacturer="Sullins Connector Solutions", Supplier Part Number 1=S1011E-04-ND, Voltage_V=1.8kV
J2 J10 J11 J12: library part CMP-0054794-2, "Header, 2.54 mm, 2x1, Gold, TH", Color=Black, Manufacturer="Wurth Elektronik", Supplier Part Number 1=732-5315-ND
J4 J5 J6 J7: library part CMP-0089624-1, Current_A=20A, Digikey Part Number=A29938CT-ND, Manufacturer="TE Connectivity", Mouser Part Number=571-638241, Operating Temperature Range="-40°C to +105°C"
J8: library part CMP-0055098-2, "Header, 2.54 mm, 6x2, Gold, TH", Color=Black, Manufacturer=Mill-Max, Supplier Part Number 1=ED1309-12-ND
Logo1: library part CMP-0074844-1
Logo2: library part CMP-0074838-1, "Texas Instrument Corporate Signature"
Logo4: library part CMP-0074769-1
MH1 MH2 MH3 MH4: library part CMP-0078424-2, "PCB Mounting Hole, No Pad", Manufacturer=Any, PartNumber=N/A
R1: library part CMP-0026737-1, "RES, 47.0 k, 1%, 0.0625 W, 0402", Manufacturer="Yageo America", Power_W=62.5mW, Supplier Part Number 1=311-47.0KLRCT-ND, TempCo="100 ppm/C", Tolerance_%=1%, Value2=0.0625W, Value_Code=47k0, ValueDisplayed=47.0k
R2 R3 R20: library part CMP-0026743-1, "RES, 820, 1%, 0.063 W, 0402", Manufacturer="Yageo America", Power_W=63mW, Supplier Part Number 1=311-820LRCT-ND, TempCo="100 ppm/C", Tolerance_%=1%, Value2=0.063W, Value_Code=820R, ValueDisplayed=820
R4 R5 R6: library part CMP-0018811-2, "RES, 330 k, 0.1%, 1 W, 1206", Manufacturer="Vishay Draloric", Power_W=1W, Supplier Part Number 1=541-2312-1-ND, TempCo="25 ppm/C", Tolerance_%=0.1%, Value_Code=330k
R7: library part CMP-0049856-1, "Var MOV 460VAC/615VDC 5000A 750V Thru-Hole Radial Bulk", Clamping Voltage=1240V, Digikey Part Number=495-6498-ND, Manufacturer=TDK, Mouser Part Number=871-B72214S2461K101, Operating Temperature Range="-40°C to +105°C", ValueDisplayed=260pF, Varistor Voltage=750V, Voltage Tolerance=10%
R8: library part CMP-0023597-2, "RES, 750, 0.1%, 0.1 W, 0603", Manufacturer="Susumu Co Ltd", Power_W=100mW, Supplier Part Number 1=RG16P750BCT-ND, TempCo="25 ppm/C", Tolerance_%=0.1%, Value2=0.1W, Value_Code=750R, ValueDisplayed=750
R9 R11 R12 R21: library part CMP-0022448-2, "RES, 49.9, 1%, 0.1 W, 0603", Manufacturer=Vishay-Dale, Power_W=100mW, Supplier Part Number 1=541-49.9HCT-ND, TempCo="100 ppm/C", Tolerance_%=1%, Value2=0.1W, Value_Code=49R9, ValueDisplayed=49.9
R10: library part CMP-0015750-2, "RES, 0.003, 1%, 3 W, AEC-Q200 Grade 0, 2512", Manufacturer=Bourns, Power_W=3W, Supplier Part Number 1=CRE2512-FZ-R003E-3CT-ND, TempCo="50 ppm/C", Tolerance_%=1%, Value_Code=3L000, ValueDisplayed=0.003
R13: library part CMP-0078821-1, "RES, 0.001, 1%, 1 W, AEC-Q200 Grade 0, 1206", Manufacturer=Bourns, Power_W=1W, TempCo="50 ppm/C", Tolerance_%=1%, Value_Code=1L000, ValueDisplayed=0.001
R14 R15 R17: library part CMP-0026769-1, "RES, 10.0 k, 0.5%, 0.063 W, 0402", Manufacturer=Vishay-Dale, Power_W=63mW, Supplier Part Number 1=541-10KAVCT-ND, TempCo="50 ppm/C", Tolerance_%=0.5%, Value2=0.063W, Value_Code=10k0, ValueDisplayed=10.0k
R16: library part CMP-0025963-3, "RES, 10.0, 1%, 0.063 W, AEC-Q200 Grade 0, 0402", Manufacturer=Vishay-Dale, Power_W=63mW, Supplier Part Number 1=541-10.0LCT-ND, TempCo="100 ppm/C", Tolerance_%=1%, Value2=0.063W, Value_Code=10R0, ValueDisplayed=10.0
R18 R19: library part CMP-0027004-1, "RES, 0, 5%, 0.063 W, 0402", Manufacturer="Yageo America", Power_W=63mW, Supplier Part Number 1=311-0.0JRCT-ND, TempCo="200 ppm/C", Tolerance_%=5%, Value2=0.063W, Value_Code=0000, ValueDisplayed=0
U1: library part CMP-0095751-1, "Mixed-Signal Microcontrollers VQFN32 ARM 32-bit Cortex-M0+ 80MHz 28 I/O's 64KB Flash 32KB SRAM", Frequency_Fixed=80MHz, Manufacturer="Texas Instruments", Max Supply Voltage=3.6V, Min Supply Voltage=1.62V, Operating Temperature Range="-40°C to +105°C"
U2: library part CMP-0093943-1, "3-Channel, Simultaneously-Sampling, 24-Bit, Reinforced Isolated DeltaSigma ADC With Integrated DC/DC Converter", Manufacturer="Texas Instruments", Max Supply Voltage=5.5V, Min Supply Voltage=3V, Operating Temperature Range="-40°C to +125°C"
U3: library part CMP-0122558-1, "1-A 16-V high-PSRR linear voltage regulator 4-SOT-223 -40 to 125", Digikey Part Number=296-TLV76133DCYRCT-ND, Dropout Voltage=0.9V, Manufacturer="Texas Instruments", Max Supply Voltage=16V, Min Supply Voltage=4.8V, Mouser Part Number=595-TLV76133DCYR, Nominal Supply Current=65uA, Operating Temperature Range="-40°C to +125°C", Output Voltage=3.3V
U4: library part CMP-0051787-3, "Dual Buffer/Driver with Open-Drain Output, DCK0006A (SOT-SC70-6)", Alternate Manufacturer="Texas Instruments", Alternate PartNumber=SN74LVC2G07DCKR, F @ Nom Voltage(Max)(Mhz)=150, Generic Part Number=SN74LVC2G07, ICC @ Nom Voltage(Max)(mA)=0.01, Operating Temperature Range(C)="-40 to 125", Rating=Catalog, tpd @ Nom Voltage(Max)(ns)=8.6,4.4,3.7,2.9, Voltage(Nom)(V)=1.8,2.5,3.3,5
Y1: library part CMP-0122603-1, "Low Jitter, High-Performance BAW Oscillator", Frequency Stability=25ppm, Manufacturer="Texas Instruments", Operating Temperature Range="-40°C to +105°C"
ZZ1: library part CMP-0003616-3
ZZ2: library part CMP-0077236-1
ZZ3: library part CMP-0077237-1
ZZ4: library part CMP-0077238-1

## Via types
v1: diameter 23.62, hole 11.81, Top Layer to Bottom Layer, 58 vias
v2: diameter 39.37, hole 19.68, Top Layer to Bottom Layer, 12 vias
v3: diameter 23.62, hole 11.81, Top Layer to Bottom Layer, tented both sides, 5 vias

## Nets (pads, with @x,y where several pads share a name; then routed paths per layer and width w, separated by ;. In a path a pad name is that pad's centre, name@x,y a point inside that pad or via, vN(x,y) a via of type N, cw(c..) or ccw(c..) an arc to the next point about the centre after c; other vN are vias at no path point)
1A: C27.1 R15.1 U4.1 | length 215.2
  Top Layer w10: U4.1@802.02,414.79 855.12,414.79 C27.1@862.2,407.7
  Top Layer w15: R15.1@843.53,263.33 862.2,282.01 C27.1@862.2,407.7
1Y: 1Y.1 C1.1 R14.1 R18.2 U4.6 | length 725.4
  Top Layer w10: 261.68,241.33 267.81,235.19 494.97,235.19 v1(494.97,233.46) ; 261.68,241.33 R18.2@261.68,265.7 ; C1.1@403.54,306.42 R14.1@455.94,306.42 457.8,304.56 v1(494.97,304.56) 501.89,311.49 671.67,311.49 1Y.1@690.22,330.04 713.44,353.26 U4.6@713.44,414.79
  Bottom Layer w10: v1(494.97,233.46) v1(494.97,304.56)
2A: R17.2 R19.2 U4.3 | length 778.4
  Top Layer w10: R19.2@346.85,277.51 356.05,268.32 731.98,268.32 v1@737.23,263.07 ; v1(757.73,524.84) R17.2@808.1,524.84 802.02,518.76 U4.3@802.02,465.97
  Bottom Layer w10: v1@737.23,263.07 737.23,264.7 757.73,285.2 v1(757.73,524.84)
  other v1: 737.84,268.25
2Y: 2Y.1 R16.1 U4.4 | length 263.9
  Top Layer w10: U4.4@713.44,465.97 740.59,465.97 749.56,457.01 749.56,350.78 770.29,330.04 2Y.1@791.78,330.04 ; 2Y.1@788.65,330.04 789.37,329.33 R16.1@789.37,263.33
A_LIN_IN: J4.1 J5.1 R4.2 R7.1 | length 3685.4
  Top Layer w39.37: R4.2@1698.88,99.69 1734.34,64.24 2179.28,64.24 2391.73,276.68 J5.1@2391.73,362.6
  Top Layer w157.48: J5.1@2391.73,362.6 J5.1@2391.73,562.6 ; J5.1@2391.73,585.15 J4.1@2391.73,1584.84 ; J4.1@2391.73,1556.89 J4.1@2391.73,1566.9 J4.1@2391.73,1756.89
  Bottom Layer w157.48: J5.1@2391.73,362.6 J5.1@2391.73,562.6 J4.1@2391.73,1566.9 J4.1@2391.73,1766.9
A_Netural_IN: C7.2 C9.1 C12.1 C15.1 C16.2 C18.1 C20.2 C22.2 C23.2 C24.2 D6.3 D7.3 FB4.2 FB6.2 HGND.1 J6.1 R7.2 R8.1 R10.2 R11.1 R13.2 U2.5 U2.6 | length 3723.6
  Top Layer w10: C24.2@1158.66,1488.01 1161.73,1488.01 C24.2@1162.23,1487.51 ; C18.1@1206.42,1760.9 C18.1@1207.7,1762.18 1244.97,1762.18 v1(1268.77,1738.38) ; C20.2@1219.72,1488.01 C20.2@1220.11,1488.4 ; C22.2@1224.17,1297.58 C22.2@1226.05,1295.69 ; 1262.56,1488.4 1263,1488.84 ; v1(1277.36,1465.07) v1@1277.36,1474.49 ; C7.2@1394.91,1595.02 1429.11,1629.22 FB6.2@1429.11,1657.7 1429.93,1658.52 1429.93,1714.62 1449.82,1734.51 1582.41,1734.51 1605.6,1711.32 1715.8,1599.65 1715.8,1335.14 1748.72,1302.22 1832.27,1302.22 1842.71,1291.77 R13.2@1842.71,1254.61
  Top Layer w15: FB4.2@1291.55,1268.24 1291.55,1259.53 1315.76,1235.31 HGND.1@1426.58,1235.31 ; C9.1@1392,1499.91 1392,1439.21 R11.1@1396.35,1434.86 ; HGND.1@1421.92,1214.8 HGND.1@1429.25,1222.13 D7.3@1429.25,1112.76
  Top Layer w20: U2.5@997.78,1456.91 U2.6@997.78,1506.91 1077.37,1506.91 C15.1@1096.77,1487.51 ; C12.1@1101.57,1297.58 C23.2@1162.23,1297.58 C22.2@1224.17,1297.58 1283.63,1297.58 1291.55,1289.66 FB4.2@1291.55,1268.24 ; C16.2@1207.99,1710.52 C18.1@1207.99,1751.6 ; C20.2@1223.92,1488.4 1262.56,1488.4 ; 1263,1488.84 v1@1277.36,1474.49 ; R11.1@1396.35,1434.86 1397.08,1435.59 R8.1@1465.78,1435.59
  Top Layer w50: R13.2@1842.72,1254.61 R10.2@2019.34,1254.37
  Top Layer w100: J6.1@2007.87,561.48 2028.43,582.04 J6.1@2032.56,586.17 ; R10.2@2027.56,1226.42 2028.43,1225.54 2028.43,991.99
  Top Layer w157.48: J6.1@2027.56,362.9 J6.1@2027.56,562.9 ; J6.1@2028.43,582.04 2028.43,991.99
  Bottom Layer w100: R7.2@2027.56,1010.75 2027.56,1126.33 2028.43,1127.2
  Bottom Layer w157.48: J6.1@2027.56,362.9 R7.2@2027.56,1010.75
  other v1: 1251.12,1252.14 1640.27,1256.91 1426.89,1283.37 1427.25,1331.14 1640.27,1351.69 1277.49,1428.25 1588.77,1445.47 1607.47,1601.98 1504.06,1613.72 1464.69,1614.77 1588.77,1659.44
  other v2: 2051.75,1132.44 2003.93,1132.78 1815.21,1179.1 1869.14,1180.09 1919.43,1194.31 1771.65,1198.36
A_Netural_OUT: FB8.2 J7.1 R10.1 R13.1 | length 1612.3
  Top Layer w10: FB8.2@1426.42,1807.91 1426.42,1771.62 1445.65,1752.39 1589.81,1752.39 1619.7,1722.5 1730.11,1612.09 1733.67,1608.53 1733.67,1342.54 1756.13,1320.09 1832.19,1320.09 1842.71,1330.61 R13.1@1842.71,1368.54 ; J7.1@2017.72,1571.9 J7.1@2027.56,1562.05
  Top Layer w50: R13.1@1842.71,1368.54 2000.25,1368.54 R10.1@2027.56,1395.85
  Top Layer w100: R10.1@2017.72,1406.34 R10.1@2027.56,1396.5 ; R10.1@2027.56,1407.65 2027.56,1562.05 J7.1@2027.56,1573.2
  Top Layer w157.48: J7.1@2017.72,1571.9 J7.1@2017.72,1756.89
  Bottom Layer w157.48: J7.1@2017.72,1546.2 J7.1@2017.72,1746.2
  other v2: 1919.43,1405.94 1823.03,1450.55 1882.91,1450.86 1940.75,1499.17 2000.25,1499.17 2049.84,1499.17
ACT: J2.1 R2.1 U1.11 | length 385
  Top Layer w10: U1.11@370.47,658.72 370.47,707.77 396.65,733.94 v1@444.73,733.94
  Top Layer w15: J2.1@593.26,681.01 622.62,651.64 R2.1@670.02,651.64
  Bottom Layer w10: v1(453.14,733.57) 540.69,733.57 J2.1@593.26,681.01
ADC_C\S\: J8.2 U2.19 | length 322.3
  Top Layer w15: v1(536.31,1279.03) 564.19,1306.91 U2.19@615.89,1306.91
  Bottom Layer w15: v1@536.37,1278.96 535.45,1145.34 596.88,1083.91 J8.2@596.88,1073.2
ADC_DIN: J8.6 U2.20 | length 310.8
  Top Layer w15: J8.6@396.88,1073.2 396.88,1100.04 553.74,1256.91 U2.20@615.89,1256.91
ADC_DOUT: J8.4 U2.12 | length 941.5
  Top Layer w15: v1(390.4,1633.99) 432.98,1676.58 544.9,1676.58 564.58,1656.91 U2.12@615.89,1656.91 ; J8.4@496.88,1073.2 499.17,1075.5 v1(499.17,1162.27)
  Bottom Layer w15: v1(390.4,1633.99) 366.56,1610.34 366.14,1356.44 366.14,1340.23 375.49,1330.89 483.73,1330.89 499.17,1315.44 v1(499.17,1162.27)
